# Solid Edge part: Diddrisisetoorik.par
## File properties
Author: Türk
Template: Iso Part.par
Last saved by: Türk
Revision: 2
Application: Solid Edge
Accuracy: 0,990
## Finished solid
Body 1: solid body, 4 faces, 3 edges, 0 vertices.
  Faces by surface: plane 2, cone 1, cylinder 1
  Edges by curve: circle 3
Bounding box of the edges (mm): 60.000 x 17.500 x 60.000, from (-30, 0, -30) to (30, 17.5, 30).
Cylindrical faces by radius (mm): R30 x1
Conical faces (half-angle, radius in mm at the cone's reference point): 45 deg R30 x1
Planar faces by outward normal: +y 1, -y 1
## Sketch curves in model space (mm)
line (0, 17.5, -14.9103) -> (0, 5, -26.9568)
line (6.4, 5, -25) -> (8, 5, -28.9137)
line (-6.4, 5, -25) -> (-8, 5, -28.9137)
line (-3.6148, 5, -25) -> (0, 5, -25)
line (-2.5, 5, -17.3205) -> (-3.6148, 5, -25)
line (-2.5, 17.5, -22.5) -> (-2.5, 17.5, -17.3205)
line (-1.8, 17.5, -12.5) -> (-2.5, 17.5, -17.3205)
line (0, 17.5, -12.5) -> (-1.8, 17.5, -12.5)
line (0, 17.5, -12.5) -> (1.8, 17.5, -12.5)
line (1.8, 17.5, -12.5) -> (2.5, 17.5, -17.3205)
line (2.5, 17.5, -17.3205) -> (2.5, 17.5, -22.5)
line (2.5, 17.5, -22.5) -> (-2.5, 17.5, -22.5)
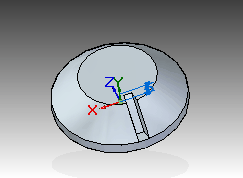
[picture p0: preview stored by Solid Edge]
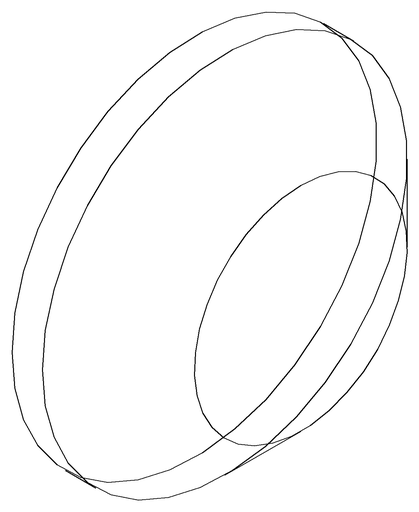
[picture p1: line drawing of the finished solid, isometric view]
